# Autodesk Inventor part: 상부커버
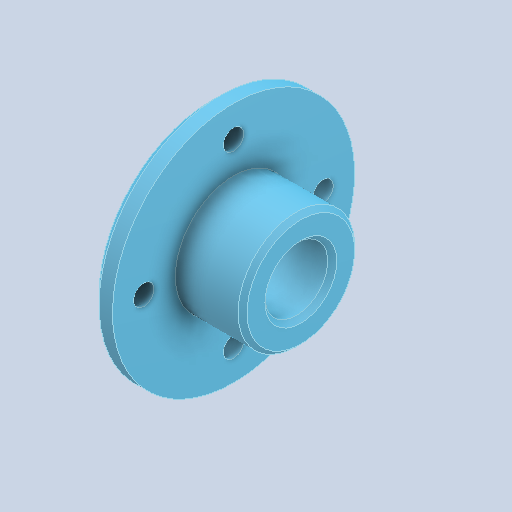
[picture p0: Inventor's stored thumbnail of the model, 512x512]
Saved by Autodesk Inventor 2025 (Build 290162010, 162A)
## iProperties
Created: 2024-07
Part Number: 상부커버
Material: 알루미늄 6061
Document SubType Name: Modeling
Designer: 학생
Density: 2.71 g/cm^3
Appearance: 기본값
Author: jhkim
Sending System: Autodesk Inventor 2025
Preprocessor: ST-DEVELOPER v20
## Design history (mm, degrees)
feature "솔리드1"
node "솔리드2"
